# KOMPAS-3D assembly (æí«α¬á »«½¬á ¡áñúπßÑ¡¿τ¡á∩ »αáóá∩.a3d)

Referenced files in D:\МОДЕЛЬ ТАНКА Т90\ДЕТАЛИ\КОРПУС\МЕТАЛЛ\КОРПУС ЛИТОЙ\: полка надгусеничная правая.m3d, брызговик правый.m3d
Referenced files in D:\МОДЕЛЬ ТАНКА Т90\ДЕТАЛИ\КОРПУС\МЕТАЛЛ\КОРПУС ШТАМПОВКА\БАКИ\: Сборка бак правый 5.a3d, Сборка бак правый 1.a3d, Сборка бак правый 2.a3d, Сборка бак правый 3.a3d, Сборка бак правый 4.a3d
Referenced files in D:\МОДЕЛЬ ТАНКА Т90\СБОРКИ\СБОРКА ЛИТЬЕ СТАРАЯ\: Сборка экран правый.a3d
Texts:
  Сборка полка надгусеничная правая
